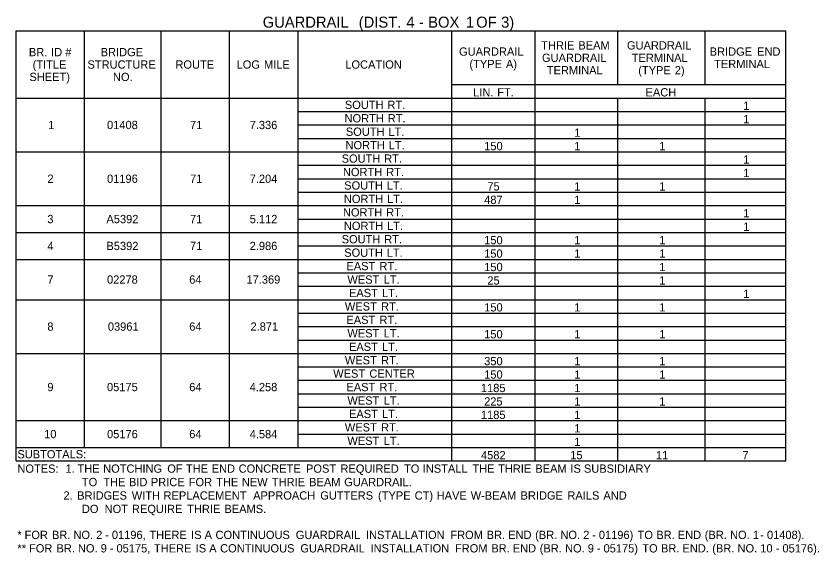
# Model space of a CAD drawing. Extents: x 540541 to 1930787, y -1948574 to 596640.
# Drawn here: x 548136 to 548719, y -1946737 to -1946346 of the extents above; entities that cross this region are included whole.
import ezdxf

# ---------------------------------------------------------------- set-up
doc = ezdxf.new("R2010")
doc.units = 0
doc.layers.add('Default', color=7, linetype='Continuous')

msp = doc.modelspace()

# ---------------------------------------------------------------- linework, layer by layer
at = {"layer": 'Default'}
for p, q in [((548135.84, -1946357.26), (548694.51, -1946357.26)), ((548135.84, -1946454.76), (548135.84, -1946357.26)), ((548135.84, -1946669.26), (548135.84, -1946357.26)), ((548185.56, -1946659.51), (548185.56, -1946357.26)), ((548241.14, -1946659.51), (548241.14, -1946357.26)), ((548290.86, -1946659.51), (548290.86, -1946357.26)), ((548340.59, -1946659.51), (548340.59, -1946357.26)), ((548452.22, -1946669.26), (548452.22, -1946357.26)), ((548512.67, -1946669.26), (548512.67, -1946357.26)), ((548572.64, -1946396.26), (548572.64, -1946357.26)), ((548636.01, -1946396.26), (548636.01, -1946357.26)), ((548694.51, -1946659.51), (548694.51, -1946357.26)), ((548452.22, -1946396.26), (548694.51, -1946396.26)), ((548512.67, -1946669.26), (548512.67, -1946396.26)), ((548135.84, -1946406.01), (548694.51, -1946406.01)), ((548572.64, -1946669.26), (548572.64, -1946406.01)), ((548572.64, -1946669.26), (548572.64, -1946406.01)), ((548636.01, -1946669.26), (548636.01, -1946406.01)), ((548636.01, -1946669.26), (548636.01, -1946406.01)), ((548340.59, -1946415.76), (548694.51, -1946415.76)), ((548340.59, -1946425.51), (548694.51, -1946425.51)), ((548340.59, -1946435.26), (548694.51, -1946435.26)), ((548135.84, -1946445.01), (548694.51, -1946445.01)), ((548340.59, -1946454.76), (548694.51, -1946454.76)), ((548340.59, -1946464.51), (548694.51, -1946464.51)), ((548135.84, -1946610.76), (548135.84, -1946474.26)), ((548340.59, -1946474.26), (548694.51, -1946474.26)), ((548135.84, -1946484.01), (548694.51, -1946484.01)), ((548340.59, -1946493.76), (548694.51, -1946493.76)), ((548135.84, -1946503.51), (548694.51, -1946503.51)), ((548340.59, -1946513.26), (548694.51, -1946513.26)), ((548135.84, -1946523.01), (548694.51, -1946523.01)), ((548340.59, -1946523.01), (548694.51, -1946523.01)), ((548340.59, -1946532.76), (548694.51, -1946532.76)), ((548340.59, -1946542.51), (548694.51, -1946542.51)), ((548135.84, -1946552.26), (548694.51, -1946552.26)), ((548340.59, -1946562.01), (548694.51, -1946562.01)), ((548340.59, -1946571.76), (548694.51, -1946571.76)), ((548340.59, -1946581.51), (548694.51, -1946581.51)), ((548135.84, -1946591.26), (548694.51, -1946591.26)), ((548340.59, -1946601.01), (548694.51, -1946601.01)), ((548340.59, -1946610.76), (548694.51, -1946610.76)), ((548340.59, -1946620.51), (548694.51, -1946620.51)), ((548135.84, -1946669.26), (548135.84, -1946630.26)), ((548340.59, -1946630.26), (548694.51, -1946630.26)), ((548135.84, -1946640.01), (548694.51, -1946640.01)), ((548340.59, -1946649.76), (548694.51, -1946649.76)), ((548135.84, -1946659.51), (548694.51, -1946659.51)), ((548340.59, -1946659.51), (548694.51, -1946659.51)), ((548694.51, -1946669.26), (548694.51, -1946659.51)), ((548135.84, -1946669.26), (548694.51, -1946669.26))]:
    msp.add_line(p, q, dxfattribs=at)

# ---------------------------------------------------------------- texts
for s, height, p in [('GUARDRAIL', 8, (548314.88, -1946354.92)), (' (DIST.', 8, (548381.61, -1946354.92)), (' 4', 8, (548416.23, -1946354.92)), (' BOX', 8, (548432.04, -1946354.92)), (' 1', 8, (548459.36, -1946354.92)), (' OF', 8, (548466.86, -1946354.92)), (' 3)', 8, (548484.97, -1946354.92)), (' -', 8, (548425.29, -1946354.92)), ('THRIE', 6, (548517.08, -1946370.76)), (' BEAM', 6, (548541.81, -1946370.76)), ('GUARDRAIL', 6, (548579.3, -1946370.76)), ('BR.', 6, (548145.17, -1946375.64)), (' ID', 6, (548159.04, -1946375.64)), (' #', 6, (548169.33, -1946375.64)), ('BRIDGE', 6, (548197.25, -1946375.64)), ('GUARDRAIL', 6, (548457.42, -1946375.26)), ('GUARDRAIL', 6, (548517.63, -1946379.76)), ('TERMINAL', 6, (548582.79, -1946379.76)), ('BRIDGE', 6, (548639.36, -1946375.26)), (' END', 6, (548671.55, -1946375.26)), ('(TITLE', 6, (548147.87, -1946384.64)), ('STRUCTURE', 6, (548187.7, -1946384.64)), ('ROUTE', 6, (548251.53, -1946384.64)), ('LOG', 6, (548295.93, -1946384.64)), (' MILE', 6, (548313.58, -1946384.64)), ('LOCATION', 6, (548374.85, -1946384.64)), ('(TYPE', 6, (548464.94, -1946384.26)), (' A)', 6, (548489.22, -1946384.26)), ('TERMINAL', 6, (548642.57, -1946384.26)), ('TERMINAL', 6, (548521.12, -1946388.76)), ('(TYPE', 6, (548587.51, -1946388.76)), (' 2)', 6, (548611.79, -1946388.76)), ('SHEET)', 6, (548145.54, -1946393.64)), ('NO.', 6, (548206.18, -1946393.64)), ('LIN.', 6, (548467.66, -1946404.81)), (' FT.', 6, (548482.91, -1946404.81)), ('EACH', 6, (548592.77, -1946404.81)), ('SOUTH', 6, (548374.52, -1946413.89)), (' RT.', 6, (548403.19, -1946413.89)), ('1', 6, (548663.7, -1946414.56)), ('NORTH', 6, (548374.29, -1946423.64)), (' RT.', 6, (548403.42, -1946423.64)), ('1', 6, (548663.7, -1946424.31)), ('1', 6, (548159.14, -1946428.51)), ('01408', 6, (548201.88, -1946428.51)), ('71', 6, (548262.11, -1946428.51)), ('7.336', 6, (548305.43, -1946428.51)), ('SOUTH', 6, (548375.22, -1946433.39)), (' LT.', 6, (548403.89, -1946433.39)), ('1', 6, (548541.09, -1946434.06)), ('NORTH', 6, (548374.99, -1946443.14)), (' LT.', 6, (548404.12, -1946443.14)), ('150', 6, (548475.66, -1946443.81)), ('1', 6, (548541.09, -1946443.81)), ('1', 6, (548602.76, -1946443.81)), ('SOUTH', 6, (548372.19, -1946452.89)), (' RT.', 6, (548400.86, -1946452.89)), ('1', 6, (548663.7, -1946453.56)), ('2', 6, (548158.59, -1946467.51)), ('01196', 6, (548201.89, -1946467.51)), ('7.204', 6, (548305.44, -1946467.51)), ('NORTH', 6, (548373.12, -1946462.64)), (' RT.', 6, (548402.26, -1946462.64)), ('1', 6, (548663.7, -1946463.31)), ('71', 6, (548262.11, -1946467.51)), ('SOUTH', 6, (548374.05, -1946472.39)), (' LT.', 6, (548402.72, -1946472.39)), ('75', 6, (548477.95, -1946473.06)), ('1', 6, (548541.09, -1946473.06)), ('1', 6, (548602.76, -1946473.06)), ('NORTH', 6, (548373.82, -1946482.14)), (' LT.', 6, (548402.95, -1946482.14)), ('487', 6, (548475.65, -1946482.81)), ('1', 6, (548541.09, -1946482.81)), ('NORTH', 6, (548373.12, -1946491.89)), (' RT.', 6, (548402.26, -1946491.89)), ('1', 6, (548663.7, -1946492.56)), ('3', 6, (548158.56, -1946496.76)), ('A5392', 6, (548201.45, -1946496.76)), ('71', 6, (548262.11, -1946496.76)), ('5.112', 6, (548305.46, -1946496.76)), ('NORTH', 6, (548373.82, -1946501.64)), (' LT.', 6, (548402.95, -1946501.64)), ('1', 6, (548663.7, -1946502.31)), ('SOUTH', 6, (548372.19, -1946511.39)), (' RT.', 6, (548400.86, -1946511.39)), ('150', 6, (548475.66, -1946512.06)), ('1', 6, (548541.09, -1946512.06)), ('1', 6, (548602.76, -1946512.06)), ('4', 6, (548158.57, -1946516.26)), ('B5392', 6, (548201.45, -1946516.26)), ('71', 6, (548262.11, -1946516.26)), ('2.986', 6, (548305.43, -1946516.26)), ('SOUTH', 6, (548374.05, -1946521.14)), (' LT.', 6, (548402.72, -1946521.14)), ('150', 6, (548475.66, -1946521.81)), ('1', 6, (548541.09, -1946521.81)), ('1', 6, (548602.76, -1946521.81)), ('EAST', 6, (548375.66, -1946530.89)), (' RT.', 6, (548397.39, -1946530.89)), ('150', 6, (548475.66, -1946531.56)), ('1', 6, (548602.76, -1946531.56)), ('7', 6, (548158.56, -1946540.64)), ('02278', 6, (548201.88, -1946540.64)), ('64', 6, (548261.54, -1946540.64)), ('17.369', 6, (548303.09, -1946540.64)), ('WEST', 6, (548376.36, -1946540.64)), (' LT.', 6, (548400.41, -1946540.64)), ('25', 6, (548477.95, -1946541.31)), ('1', 6, (548602.76, -1946541.31)), ('EAST', 6, (548377.52, -1946550.39)), (' LT.', 6, (548399.25, -1946550.39)), ('1', 6, (548663.7, -1946551.06)), ('WEST', 6, (548374.5, -1946560.14)), (' RT.', 6, (548398.55, -1946560.14)), ('150', 6, (548475.66, -1946560.81)), ('1', 6, (548541.09, -1946560.81)), ('1', 6, (548602.76, -1946560.81)), ('EAST', 6, (548375.66, -1946569.89)), (' RT.', 6, (548397.39, -1946569.89)), ('8', 6, (548158.55, -1946574.76)), ('03961', 6, (548202.47, -1946574.76)), ('64', 6, (548261.54, -1946574.76)), ('2.871', 6, (548306.01, -1946574.76)), ('WEST', 6, (548376.36, -1946579.64)), (' LT.', 6, (548400.41, -1946579.64)), ('150', 6, (548475.66, -1946580.31)), ('1', 6, (548541.09, -1946580.31)), ('1', 6, (548602.76, -1946580.31)), ('EAST', 6, (548377.52, -1946589.39)), (' LT.', 6, (548399.25, -1946589.39)), ('WEST', 6, (548374.5, -1946599.14)), (' RT.', 6, (548398.55, -1946599.14)), ('350', 6, (548475.66, -1946599.81)), ('1', 6, (548541.09, -1946599.81)), ('1', 6, (548602.76, -1946599.81)), ('WEST', 6, (548366.04, -1946608.89)), (' CENTER', 6, (548390.09, -1946608.89)), ('150', 6, (548475.66, -1946609.56)), ('1', 6, (548541.09, -1946609.56)), ('1', 6, (548602.76, -1946609.56)), ('9', 6, (548158.55, -1946618.64)), ('05175', 6, (548201.86, -1946618.64)), ('64', 6, (548261.54, -1946618.64)), ('4.258', 6, (548305.42, -1946618.64)), ('EAST', 6, (548375.66, -1946618.64)), (' RT.', 6, (548397.39, -1946618.64)), ('1185', 6, (548473.29, -1946619.31)), ('1', 6, (548541.09, -1946619.31)), ('WEST', 6, (548376.36, -1946628.39)), (' LT.', 6, (548400.41, -1946628.39)), ('225', 6, (548475.62, -1946629.06)), ('1', 6, (548541.09, -1946629.06)), ('1', 6, (548602.76, -1946629.06)), ('EAST', 6, (548377.52, -1946638.14)), (' LT.', 6, (548399.25, -1946638.14)), ('1185', 6, (548473.29, -1946638.81)), ('1', 6, (548541.09, -1946638.81)), ('WEST', 6, (548374.5, -1946647.89)), (' RT.', 6, (548398.55, -1946647.89)), ('10', 6, (548156.24, -1946652.76)), ('05176', 6, (548201.89, -1946652.76)), ('64', 6, (548261.54, -1946652.76)), ('4.584', 6, (548305.44, -1946652.76)), ('1', 6, (548541.09, -1946648.56)), ('WEST', 6, (548376.36, -1946657.64)), (' LT.', 6, (548400.41, -1946657.64)), ('1', 6, (548541.09, -1946658.31)), ('SUBTOTALS:', 6, (548136.81, -1946667.39)), ('4582', 6, (548473.34, -1946668.06)), ('15', 6, (548538.12, -1946668.06)), ('11', 6, (548600.34, -1946668.06)), ('7', 6, (548663.12, -1946668.06)), ('NOTES:', 6, (548136.81, -1946677.81)), ('  1.', 6, (548167.29, -1946677.81)), (' THE', 6, (548178.2, -1946677.81)), (' NOTCHING', 6, (548196.85, -1946677.81)), (' OF', 6, (548243.37, -1946677.81)), (' THE', 6, (548256.95, -1946677.81)), (' END', 6, (548275.6, -1946677.81)), (' CONCRETE', 6, (548295.18, -1946677.81)), (' POST', 6, (548344.11, -1946677.81)), (' REQUIRED', 6, (548369.1, -1946677.81)), (' TO', 6, (548415.23, -1946677.81)), (' INSTALL', 6, (548428.83, -1946677.81)), (' THE', 6, (548464.87, -1946677.81)), (' THRIE', 6, (548483.52, -1946677.81)), (' BEAM', 6, (548510.55, -1946677.81)), (' IS', 6, (548536.01, -1946677.81)), (' SUBSIDIARY', 6, (548545.82, -1946677.81)), ('                     TO', 6, (548136.81, -1946687.56)), (' THE', 6, (548196.96, -1946687.56)), (' BID', 6, (548215.61, -1946687.56)), (' PRICE', 6, (548231.47, -1946687.56)), (' FOR', 6, (548258.97, -1946687.56)), (' THE', 6, (548278.88, -1946687.56)), (' NEW', 6, (548297.53, -1946687.56)), (' THRIE', 6, (548319.32, -1946687.56)), (' BEAM', 6, (548346.35, -1946687.56)), (' GUARDRAIL.', 6, (548371.81, -1946687.56)), ('               2.', 6, (548136.81, -1946697.31)), (' BRIDGES', 6, (548177.98, -1946697.31)), (' WITH', 6, (548217.61, -1946697.31)), (' REPLACEMENT', 6, (548240.68, -1946697.31)), (' APPROACH', 6, (548305.73, -1946697.31)), (' GUTTERS', 6, (548354.44, -1946697.31)), (' (TYPE', 6, (548396.39, -1946697.31)), (' CT)', 6, (548422.96, -1946697.31)), (' HAVE', 6, (548438.95, -1946697.31)), (' W-BEAM', 6, (548463.66, -1946697.31)), (' BRIDGE', 6, (548499.82, -1946697.31)), (' RAILS', 6, (548533.85, -1946697.31)), (' AND', 6, (548559.97, -1946697.31)), ('                     DO', 6, (548136.81, -1946707.06)), (' NOT', 6, (548197.89, -1946707.06)), (' REQUIRE', 6, (548217.75, -1946707.06)), (' THRIE', 6, (548257.83, -1946707.06)), (' BEAMS.', 6, (548284.86, -1946707.06)), ('*', 6, (548136.81, -1946725.89)), (' FOR', 6, (548139.78, -1946725.89)), (' BR.', 6, (548159.69, -1946725.89)), (' NO.', 6, (548175.26, -1946725.89)), (' 2', 6, (548191.76, -1946725.89)), (' -', 6, (548198.31, -1946725.89)), (' 01196,', 6, (548203.16, -1946725.89)), (' THERE', 6, (548230.37, -1946725.89)), (' IS', 6, (548260.67, -1946725.89)), (' A', 6, (548270.48, -1946725.89)), (' CONTINUOUS', 6, (548278.41, -1946725.89)), (' GUARDRAIL', 6, (548336.66, -1946725.89)), (' INSTALLATION', 6, (548387.61, -1946725.89)), (' FROM', 6, (548448.88, -1946725.89)), (' BR.', 6, (548475.26, -1946725.89)), (' END', 6, (548490.83, -1946725.89)), (' (BR.', 6, (548510.41, -1946725.89)), (' NO.', 6, (548528.77, -1946725.89)), (' 2', 6, (548545.27, -1946725.89)), (' -', 6, (548551.82, -1946725.89)), (' 01196)', 6, (548556.67, -1946725.89)), (' TO', 6, (548584.79, -1946725.89)), (' BR.', 6, (548598.38, -1946725.89)), (' END', 6, (548613.96, -1946725.89)), (' (BR.', 6, (548633.54, -1946725.89)), (' NO.', 6, (548651.9, -1946725.89)), (' 1', 6, (548668.4, -1946725.89)), (' -', 6, (548673.85, -1946725.89)), (' 01408).', 6, (548678.7, -1946725.89)), (' FOR', 6, (548143.04, -1946735.64)), (' NO.', 6, (548178.52, -1946735.64)), (' 9', 6, (548195.02, -1946735.64)), (' 05175,', 6, (548206.5, -1946735.64)), (' IS', 6, (548264, -1946735.64)), (' CONTINUOUS', 6, (548281.75, -1946735.64)), (' GUARDRAIL', 6, (548340, -1946735.64)), (' INSTALLATION', 6, (548390.94, -1946735.64)), (' FROM', 6, (548452.21, -1946735.64)), (' (BR.', 6, (548513.74, -1946735.64)), (' NO.', 6, (548532.11, -1946735.64)), (' 9', 6, (548548.61, -1946735.64)), (' 05175)', 6, (548560.08, -1946735.64)), (' TO', 6, (548588.2, -1946735.64)), (' (BR.', 6, (548638.99, -1946735.64)), (' NO.', 6, (548657.35, -1946735.64)), (' 10', 6, (548673.85, -1946735.64)), (' 05176).', 6, (548689.95, -1946735.64)), ('**', 6, (548136.81, -1946735.64)), (' BR.', 6, (548162.95, -1946735.64)), (' -', 6, (548201.64, -1946735.64)), (' THERE', 6, (548233.71, -1946735.64)), (' A', 6, (548273.81, -1946735.64)), (' BR.', 6, (548478.59, -1946735.64)), (' END', 6, (548494.16, -1946735.64)), (' -', 6, (548555.22, -1946735.64)), (' BR.', 6, (548601.79, -1946735.64)), (' END.', 6, (548617.36, -1946735.64)), (' -', 6, (548685.1, -1946735.64))]:
    msp.add_text(s, height=height, dxfattribs=at).set_placement(p)

doc.saveas('drawing.dxf')
